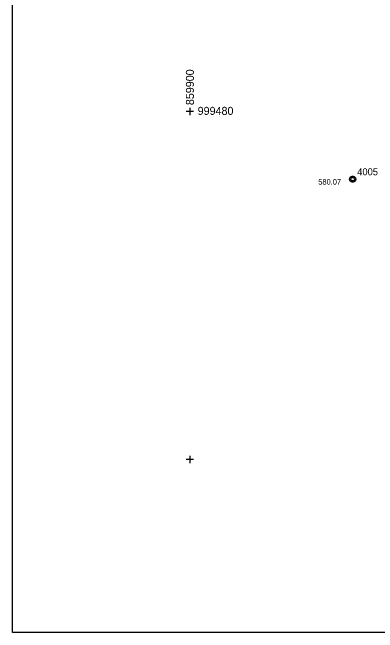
# Model space of a CAD drawing. Extents: x -859910.5 to -859850.8, y -999510 to -999424.1.
# Drawn here: x -859910.19 to -859889.21, y -999509.95 to -999474.31 of the extents above; entities that cross this region are included whole.
import ezdxf

# ---------------------------------------------------------------- set-up
doc = ezdxf.new("R2010")
doc.units = 0
for name, color, linetype in [('Bod_BP', 7, 'Continuous'), ('Formát', 7, 'Continuous'), ('Síť křížek', 7, 'Continuous'), ('Výška bodu_BP', 7, 'Continuous'), ('Číslo bodu_BP', 7, 'Continuous')]:
    doc.layers.add(name, color=color, linetype=linetype)

msp = doc.modelspace()

# ---------------------------------------------------------------- linework, layer by layer
at = {"layer": 'Bod_BP'}
msp.add_lwpolyline([(-859890.64, -999484.062), (-859890.671, -999484.062), (-859890.728, -999484.041), (-859890.775, -999484.002), (-859890.805, -999483.949), (-859890.816, -999483.889), (-859890.805, -999483.829), (-859890.775, -999483.776), (-859890.728, -999483.737), (-859890.671, -999483.716), (-859890.61, -999483.716), (-859890.553, -999483.737), (-859890.506, -999483.776), (-859890.476, -999483.829), (-859890.465, -999483.889), (-859890.476, -999483.949), (-859890.506, -999484.002), (-859890.553, -999484.041), (-859890.61, -999484.062), (-859890.64, -999484.062)], dxfattribs=at)
msp.add_lwpolyline([(-859890.618, -999483.793), (-859890.578, -999483.812), (-859890.55, -999483.847), (-859890.54, -999483.89), (-859890.55, -999483.933), (-859890.578, -999483.968), (-859890.618, -999483.987), (-859890.662, -999483.987), (-859890.702, -999483.968), (-859890.73, -999483.933), (-859890.74, -999483.89), (-859890.73, -999483.847), (-859890.702, -999483.812), (-859890.662, -999483.793)], close=True, dxfattribs=at)
at = {"layer": 'Formát'}
msp.add_lwpolyline([(-859910.19, -999425.951), (-859850.79, -999425.951), (-859850.79, -999509.951), (-859910.19, -999509.951)], close=True, dxfattribs=at)
at = {"layer": 'Síť křížek'}
for p, q in [((-859900, -999479.788), (-859900, -999480.212)), ((-859899.788, -999480), (-859900.212, -999480)), ((-859900, -999499.788), (-859900, -999500.212)), ((-859899.788, -999500), (-859900.212, -999500))]:
    msp.add_line(p, q, dxfattribs=at)

# ---------------------------------------------------------------- texts
for s, rotation, p in [('859900', 90, (-859899.76, -999479.642)), ('999480', 360, (-859899.546, -999480.203))]:
    msp.add_text(s, height=0.4608, rotation=rotation, dxfattribs=at).set_placement(p)
at = {"layer": 'Výška bodu_BP'}
msp.add_text('580.07 ', height=0.32, dxfattribs=at).set_placement((-859892.615, -999484.21))
at = {"layer": 'Číslo bodu_BP'}
msp.add_text(' 4005', height=0.4, dxfattribs=at).set_placement((-859890.525, -999483.672))

doc.saveas('drawing.dxf')
